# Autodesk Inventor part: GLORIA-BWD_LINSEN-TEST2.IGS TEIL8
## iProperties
Created: 2005-04
Part Number: GLORIA-BWD_LINSEN-TEST2.IGS TEIL8
Document SubType Name: Modeling
Designer: Nordmeyer
Manufacturer: Standard
Standards Organization: Custom
Author: Nordmeyer
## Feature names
1. Erst1
